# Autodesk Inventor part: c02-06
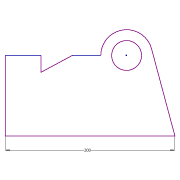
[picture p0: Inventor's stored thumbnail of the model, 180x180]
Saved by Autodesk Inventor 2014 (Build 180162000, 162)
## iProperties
Created: 2013-02
Part Number: c02-06
Material: Generic
Document SubType Name: Modeling
Designer: Thom Tremblay
Density: 1 g/cm^3
Appearance: Default
Author: Thom Tremblay
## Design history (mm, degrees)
sketch "Sketch1"
  geometry: L1 (114.675, -56.038)-(87.066, 47.002); L2 (-85.325, 39.118)-(-85.325, -56.038); L3 (-85.325, -56.038)-(114.675, -56.038); L4 (-43.342, 39.118)-(-43.342, 19.274); L5 (27.177, 39.118)-(-6.543, 39.118); L6 (-43.342, 39.118)-(-85.325, 39.118); L7 (-43.342, 19.274)-(-6.543, 39.118); C1 r 17.66 at (57.64, 39.118); A1 r 30.464 centre (57.64, 39.118) between (87.066, 47.002) and (27.177, 39.118)
  constraints: 14 end point, 2 centre point, 2 parallel, 2 perpendicular, 2 point on circle, 2 tangent, 1 collinear, 1 concentric, 1 point on line, 1 vertical, 1 other
  dimensions: "d0" = 200 distance of L2.end L1.start
